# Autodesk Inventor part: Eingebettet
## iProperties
Created: 2008-02
Part Number: Eingebettet
Document SubType Name: Modeling
Designer: mp
Density: 1 g/cm^3
Author: mp
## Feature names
1. Extrusion1
